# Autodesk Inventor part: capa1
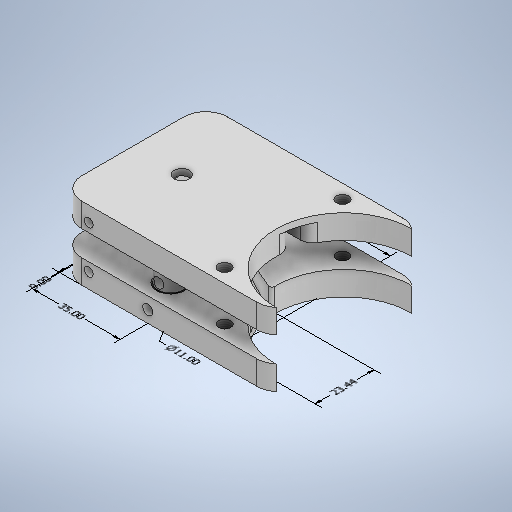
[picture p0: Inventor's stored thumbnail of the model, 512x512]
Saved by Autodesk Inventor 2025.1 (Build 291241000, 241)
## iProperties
Created: 2026-01
Part Number: capa1
Material: Genérico
Document SubType Name: Modeling
Designer: Usuario
Density: 1 g/cm^3
Appearance: Valor por defecto
Author: Usuario
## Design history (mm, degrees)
node "Anotaciones"
  node "Cota lineal 1" dims "d0" = 84 (= altura), "d1" = 58 (= base), "d2" = 1, "d4" = 18.5 (= 0.5 x D_polea_metal + 2 x margen_canal), "d7" = 21 (= D_polea_metal), "d8" = 9, "d9" = 5, "d43" = 174, "d64" = 35 (derived)
  node "Cota de diámetro 1" dims "d0" = 84 (= altura), "d1" = 58 (= base), "d2" = 1, "d4" = 18.5 (= 0.5 x D_polea_metal + 2 x margen_canal), "d7" = 21 (= D_polea_metal), "d8" = 9, "d9" = 5, "d43" = 174, "d66" = 11 (derived)
  node "Cota lineal 2" dims "d0" = 84 (= altura), "d1" = 58 (= base), "d2" = 1, "d4" = 18.5 (= 0.5 x D_polea_metal + 2 x margen_canal), "d7" = 21 (= D_polea_metal), "d8" = 9, "d9" = 5, "d43" = 174, "d68" = 9 (derived)
  node "Cota lineal 3" dims "d0" = 84 (= altura), "d1" = 58 (= base), "d2" = 1, "d4" = 18.5 (= 0.5 x D_polea_metal + 2 x margen_canal), "d7" = 21 (= D_polea_metal), "d8" = 9, "d9" = 5, "d43" = 174, "d91" = 40.5 (derived)
  node "Cota lineal 4" dims "d0" = 84 (= altura), "d1" = 58 (= base), "d2" = 1, "d4" = 18.5 (= 0.5 x D_polea_metal + 2 x margen_canal), "d7" = 21 (= D_polea_metal), "d8" = 9, "d9" = 5, "d43" = 174, "d92" = 23.435 (derived)
sketch "Boceto1" dims "d7" = 21 (= D_polea_metal)
  geometry: L1 (-84, -58)-(0, -58); L2 (0, -58)-(0, 0); L3 (0, -29)-(-1, -29); L4 (0, -29)-(1, -29); L5 (-1, -29)-(-19.5, -29); L6 (-84, 0)-(-84, -2); L7 (-84, -56)-(-84, -58); L8 (0, 0)-(-9, 0); L9 (-9, 0)-(-9, -19); L10 (-14, 0)-(-14, -15.584); L11 (-19.5, -29)-(-19.5, -18.5); L12 (0, 0)-(-9, 0); L13 (-14, 0)-(-84, 0); A1 r 86 centre (-86.014, -107.886) between (-35.979, -37.939) and (-57.082, -26.898); A2 r 9.226 centre (-30.611, -30.435) between (-35.979, -37.939) and (-29.412, -39.583); A3 r 14.5 centre (-19.5, -29) between (-14, -15.584) and (-32.42, -35.583); A4 r 14.5 centre (-19.5, -29) between (-29.412, -39.583) and (-9, -19); A5 r 174 centre (-146.773, -166.729) between (-32.42, -35.583) and (-60.569, -15.584); A6 r 27 centre (-84, -29) between (-84, -56) and (-57.082, -26.898); A7 r 27 centre (-84, -29) between (-60.569, -15.584) and (-84, -2)
  constraints: 26 end point, 14 point on circle, 7 centre point, 5 horizontal, 5 parallel, 4 perpendicular, 2 coincident, 1 collinear, 1 midpoint, 1 tangent, 1 vertical, 1 vertical alignment, 2 other
  dimensions: "d0" = 84 distance of L1.end L1.start (= altura); "d1" = 58 distance of L1.start L6.start (= base); "d2" = 1 distance of L3.start L3.end; "d4" = 18.5 distance of L3.end L5.end (= 0.5 x D_polea_metal + 2 x margen_canal); "d8" = 9 distance of L2.end L8.end; "d9" = 5 distance of L8.end L10.start; "d43" = 174 radius of A5
extrude "prototipoInterno" new body sketch "Boceto1" distance "d14" = 7 (= espesor_polea_metalica); taper "d15" = 0 deg
node "Plano de trabajo1"
sketch "Boceto2"
  geometry: L1 (0, 0)-(58, 0) reference; L2 (2, 84)-(0, 84) reference; L3 (58, 0)-(0, 0); L4 (0, 0)-(0, 84); L5 (0, 84)-(58, 84); L6 (58, 84)-(58, 0); 2 further points
  constraints: 8 end point, 2 parallel, 1 horizontal, 1 perpendicular
extrude "c1" join sketch "Boceto2" distance "d16" = 2.5 (= margen_cara_lateral); taper "d17" = 0 deg
sketch "Boceto3"
  geometry: C1 r 3 at (19.5, 29); A1 r 14.5 centre (19.5, 29) between (9, 39) and (29.412, 18.417) reference; 1 further point
  constraints: 1 centre point, 1 coincident
  dimensions: "d18" = 6 diameter of C1 (= D_interno_polea_metal)
node "Plano de trabajo2"
sketch "Boceto4"
  geometry: L1 (0, 14)-(7, 14) reference; L2 (0, 9)-(7, 9) reference; L3 (7, 9)-(0, 9); L4 (0, 9)-(0, 14); L5 (0, 14)-(7, 14); L6 (7, 14)-(7, 9); C1 r 1.75 at (3.5, 11.5); 5 further points
  constraints: 8 end point, 2 parallel, 1 centre point, 1 horizontal, 1 perpendicular
  dimensions: "d21" = 3.5 diameter of C1 (computed from margen_canal)
extrude "entradaCable" join sketch "Boceto4" stored distance "d22" = 2.5 (derived); taper "d23" = 0 deg
node "Plano de trabajo3"
node "plano_sym"
mirror "Simetría1"
node "Plano de trabajo5"
sketch "Boceto6"
  geometry: L1 (18.417, 29.412)-(18.417, 75.618); L2 (22.417, 32.42)-(22.417, 72.214); A1 r 14.5 centre (29, 19.5) between (22.417, 32.42) and (18.417, 29.412); A2 r 13.5 centre (29, 84) between (18.417, 75.618) and (22.417, 72.214); 4 further points
  constraints: 4 end point, 4 point on circle, 2 centre point, 2 coincident, 1 parallel, 1 vertical
extrude "conductoRecto" cut sketch "Boceto6" stored distance "d28" = 10; taper "d29" = 0 deg
sketch "Boceto7"
  geometry: L1 (0, 84)-(58, 84) reference; L2 (22.417, 57.815)-(22.417, 32.42); L3 (22.417, 39.449)-(22.417, 57.815) reference; L4 (0, 84)-(58, 84) reference; L5 (44.488, 61.884)-(43.5, 19.5); A1 r 90 centre (-49.886, 86.014) between (22.417, 32.42) and (39.5, 75.515) reference; A2 r 14.5 centre (29, 19.5) between (39.5, 29.5) and (22.417, 32.42); A3 r 27 centre (29, 84) between (22.417, 57.815) and (44.488, 61.884); A4 r 14.5 centre (29, 19.5) between (18.417, 29.412) and (22.417, 32.42) reference; 3 further points
  constraints: 5 point on circle, 4 end point, 2 centre point, 1 coincident, 1 collinear, 1 midpoint
  dimensions: "d45" = 54 diameter of A3 (= 2 x R_polea_driven)
extrude "rellenoASym" join sketch "Boceto7" stored distance "d30" = 10; taper "d31" = 0 deg
extrude "varillaEjePoleas" cut sketch "Boceto3" stored distance "d40" = 10; taper "d41" = 0 deg
fillet "Empalme1" dims "d32" = 12
fillet "Empalme2" dims "d33" = 1
fillet "Empalme3" dims "d34" = 5
fillet "Empalme4" dims "d35" = 1
fillet "Empalme5" dims "d36" = 1
fillet "Empalme9" dims "d44" = 5
fillet "Empalme10" dims "d46" = 5
fillet "Empalme11" dims "d47" = 5
sketch "Boceto8"
  geometry: L1 (0, 84)-(58, 84) reference; L2 (2, 84)-(56, 84); A1 r 27 centre (29, 84) between (2, 84) and (56, 84); 1 further point
  constraints: 2 end point, 2 point on circle, 2 point on line, 1 centre point, 1 midpoint
extrude "fix" cut sketch "Boceto8" extent not by distance; stored distance "d48" = 10; taper "d49" = 0 deg
mirror "Simetría2"
fillet "Empalme12" dims "d50" = 8.75
fillet "Empalme13" dims "d51" = 9
fillet "Empalme14" dims "d52" = 9
fillet "fix_entradaCable" dims "d53" = 2
mirror "Simetría5"
node "Plano de trabajo6"
sketch "Boceto9"
  geometry: L1 (0, 0)-(35, 0); L2 (8.75, 0)-(78.343, 0) reference; L3 (35, 0)-(35, 9); L4 (0, 29)-(36.381, 29); C1 r 5 at (35, 9); C2 r 5 at (35, 49)
  constraints: 6 end point, 2 centre point, 1 coincident, 1 horizontal, 1 perpendicular, 1 point on line, 1 symmetric about line, 1 other
  dimensions: "d54" = 35 distance of L1.start L1.end; "d55" = 9 distance of L1.end L3.end; "d56" = 10 diameter of C1
extrude "SalidaAcople" join sketch "Boceto9" distance "d57" = 11.5 (= extrusion_acople); taper "d58" = 0 deg
sketch "Boceto10"
  geometry: L1 (0, 0)-(0, -35); L2 (0, -78.343)-(0, -8.75) reference; L3 (0, -35)-(9, -35); L4 (8.75, 0)-(49.25, 0) reference; L5 (29, 0)-(29, -6.596); C1 r 5.5 at (9, -35); C2 r 5.5 at (49, -35); 1 further point
  constraints: 6 end point, 2 centre point, 1 coincident, 1 midpoint, 1 perpendicular, 1 point on line, 1 symmetric about line, 1 vertical, 1 other
  dimensions: "d59" = 35 distance of L1.start L1.end; "d60" = 9 distance of L1.end L3.end; "d61" = 11 diameter of C1
extrude "EntradaAcople" cut sketch "Boceto10" extent not by distance; stored distance "d62" = 0; taper "d63" = 0 deg
sketch "Boceto11"
  geometry: L1 (7, 0)-(-2.5, 0) reference; L2 (0, 0)-(-2.5, 0); L3 (-2.5, 0)-(-2.5, 35); L4 (-2.5, 35)-(2.25, 35); C1 r 2 at (2.25, 35)
  constraints: 6 end point, 2 perpendicular, 1 centre point, 1 coincident, 1 horizontal
  dimensions: "d79" = 35 distance of L1.end L3.end; "d80" = 4.75 distance of L3.end L4.end; "d81" = 4 diameter of C1
extrude "seguro" cut sketch "Boceto11" distance "d72" = 12; taper "d73" = 0 deg
sketch "Boceto12"
  geometry: L1 (0, 0)-(0, 35); L2 (0, 35)-(9.5, 35); C1 r 2 at (9.5, 35)
  constraints: 4 end point, 1 centre point, 1 coincident, 1 perpendicular, 1 vertical
  dimensions: "d74" = 35 distance of L1.start L1.end; "d75" = 9.5 distance of L1.end L2.end (computed from dist_plano_sym); "d76" = 4 diameter of C1
extrude "entradaSeguro" cut sketch "Boceto12" distance "d77" = 16; taper "d78" = 0 deg
node "plano_sagital"
mirror "Simetría6"
sketch "Boceto13"
  geometry: L1 (29, 0)-(29, -60); L2 (29, -60)-(5.565, -60); C1 r 2.425 at (5.565, -60); C2 r 2.425 at (52.435, -60); 1 further point
  constraints: 4 end point, 2 centre point, 1 coincident, 1 horizontal, 1 symmetric about line, 1 other
  dimensions: "d82" = 60 distance of L1.start L1.end (computed from altura); "d83" = 23.435 distance of L1.end L2.end (= 0.5 x dist_between_screws); "d84" = 4.85 diameter of C1 (= d_screws)
extrude "tornillos" cut sketch "Boceto13" extent not by distance; stored distance "d85" = 0; taper "d86" = 0 deg
feature "Rosca1" dims "d87" = 9.5, "d88" = 0
feature "Rosca2" dims "d89" = 9.5, "d90" = 0
mirror "Simetría7"
node "Sólido1"
other parameters: "base" = 58 (computed from R_polea_driven) [user parameter; used in 1 equation term], "altura" = 84 (computed from dist_poleas, D_polea_metal, margen_canal) [user parameter; used in 2 equation terms], "dist_poleas" = 57.5 (computed from D_polea_metal, R_polea_driven) [user parameter; used in 1 equation term], "R_polea_driven" = 27 [user parameter; used in 5 equation terms], "D_polea_metal" = 21 [user parameter; used in 5 equation terms], "margen_canal" = 4 [user parameter; used in 4 equation terms], "d5" = 29 (= D_polea_metal + 2 x margen_canal), "d6" = 27 (= R_polea_driven), "espesor_polea_metalica" = 7 [user parameter; used in 1 equation term], "margen_cara_lateral" = 2.5 [user parameter; used in 1 equation term], "D_interno_polea_metal" = 6 [user parameter; used in 1 equation term], "d26" = 5 (= dist_plano_sym), "dist_plano_sym" = 5 [user parameter; used in 2 equation terms], "d42" = 54 (= 2 x R_polea_driven), "extrusion_acople" = 11.5 [user parameter; used in 1 equation term], "dist_between_screws" = 46.87 [user parameter; used in 1 equation term], "d_screws" = 4.85 [user parameter; used in 1 equation term], "d65" = 15.24285 (derived), "d67" = 5.80371 (derived)
